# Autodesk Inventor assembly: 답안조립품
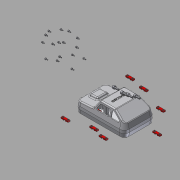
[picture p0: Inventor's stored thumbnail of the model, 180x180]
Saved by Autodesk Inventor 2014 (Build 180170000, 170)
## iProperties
Created: 2015-05
Part Number: 답안조립품
Document SubType Name: Assembly
Designer: Administrator
Author: Administrator
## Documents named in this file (7)
- C:\Documents and Settings\Administrator\바탕 화면\450508V1020\답안조립품.iam
- C:\Documents and Settings\Administrator\바탕 화면\450508V1020\본체.ipt
- C:\Documents and Settings\Administrator\바탕 화면\450508V1020\커버.ipt
- C:\Documents and Settings\Administrator\바탕 화면\450508V1020\바퀴.ipt
- C:\Documents and Settings\Administrator\바탕 화면\450508V1020\바퀴고정부.ipt
- C:\Documents and Settings\Administrator\바탕 화면\450508V1020\M4x10.ipt
- C:\Documents and Settings\Administrator\바탕 화면\450508V1020\M2x4.ipt
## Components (20 placed, 2 different names)
1. M4x10:1
2. M4x10:2
3. M4x10:3
4. M4x10:4
5. M2x4:1
6. M2x4:2
7. M2x4:3
8. M2x4:4
9. M2x4:5
10. M2x4:6
11. M2x4:7
12. M2x4:8
13. M2x4:9
14. M2x4:10
15. M2x4:11
16. M2x4:12
17. M2x4:13
18. M2x4:14
19. M2x4:15
20. M2x4:16
